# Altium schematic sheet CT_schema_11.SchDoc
size 146 x 119 mm
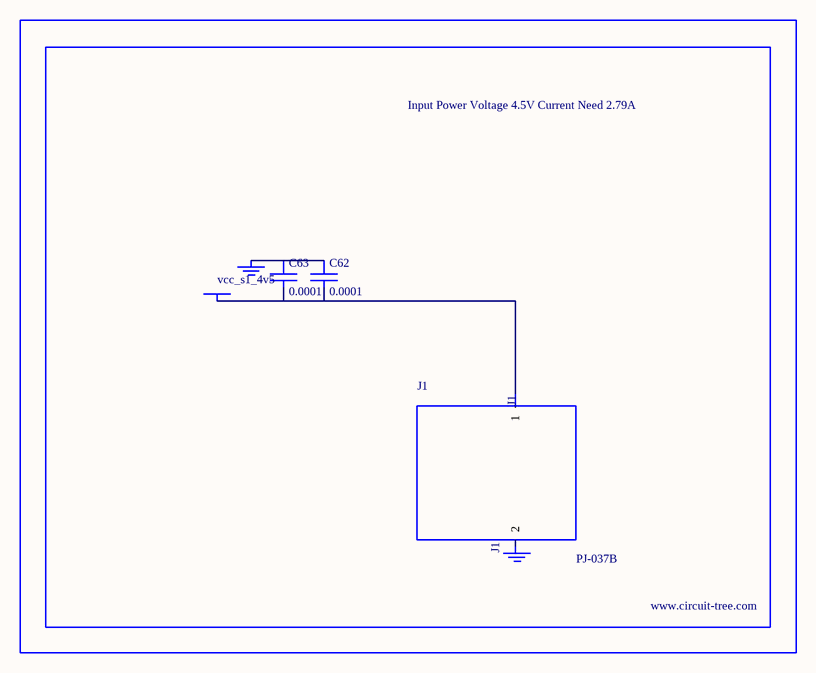
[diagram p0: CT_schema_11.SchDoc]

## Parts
BORDER10  (no value)
C62  0.0001  [EXV-9H]
C63  0.0001  [EXV-9H]
GND_INSTANCE_10_0  (no value)
GND_INSTANCE_10_1  (no value)
J1  PJ-037B  [PJ-037B_PACKAGE]
POWER_INSTANCE_10_0  vcc_s1_4v5

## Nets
NetC62_1: C62.1 C63.1 GND_INSTANCE_10_0.0(GND)
NetC62_2: C62.2 C63.2 J1.1 POWER_INSTANCE_10_0.0(PWR)

Not connected (* = marked no-connect by the designer): GND_INSTANCE_10_1 0(GND); J1 2

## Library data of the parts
BORDER10 = BORDER_PAGE10
C62 C63 = EDK107M035A9HAA
GND_INSTANCE_10_0 GND_INSTANCE_10_1 = GND
POWER_INSTANCE_10_0 = PWR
